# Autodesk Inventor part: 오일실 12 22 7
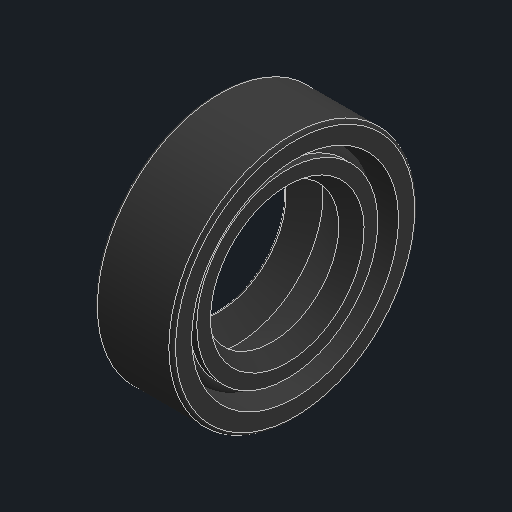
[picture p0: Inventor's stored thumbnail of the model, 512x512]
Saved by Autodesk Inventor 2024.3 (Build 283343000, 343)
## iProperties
Created: 2024-05
Part Number: 오일실 12 22 7
Material: 고무
Description: 오일-실
Document SubType Name: Modeling
Designer: MyPc
Density: 0.93 g/cm^3
Appearance: 기본값
Author: jhkim
Sending System: Autodesk Inventor 2025
Preprocessor: ST-DEVELOPER v20
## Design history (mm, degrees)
node "오일실 12 22 71"
node "솔리드1"
body "Solid1"
